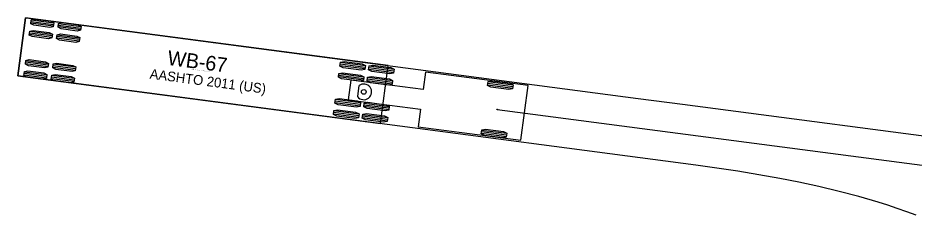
# Model space of a CAD drawing. Extents: x 2175591 to 2194071, y 76570 to 86955.
# Drawn here: x 2192726.8 to 2192856.7, y 86661.3 to 86689.9 of the extents above; entities that cross this region are included whole.
import ezdxf

# ---------------------------------------------------------------- set-up
doc = ezdxf.new("R2010")
doc.units = 0
doc.layers.add('-NOPLT', color=7, linetype='Continuous')

msp = doc.modelspace()

# ---------------------------------------------------------------- linework, layer by layer
at = {"layer": '-NOPLT'}
for p, q in [((2192727.88, 86689.91), (2192726.77, 86681.48)), ((2192780.43, 86683), (2192727.88, 86689.91)), ((2192731.93, 86688.91), (2192728.66, 86689.34)), ((2192731.96, 86689.14), (2192728.69, 86689.57)), ((2192731.9, 86688.69), (2192728.63, 86689.12)), ((2192735.87, 86688.16), (2192732.6, 86688.59)), ((2192735.9, 86688.39), (2192732.63, 86688.82)), ((2192735.93, 86688.62), (2192732.66, 86689.05)), ((2192731.69, 86687.05), (2192728.42, 86687.48)), ((2192731.72, 86687.28), (2192728.45, 86687.71)), ((2192731.75, 86687.5), (2192728.48, 86687.93)), ((2192735.66, 86686.53), (2192732.38, 86686.96)), ((2192735.69, 86686.76), (2192732.41, 86687.19)), ((2192735.72, 86686.98), (2192732.44, 86687.41)), ((2192731.13, 86682.8), (2192727.86, 86683.23)), ((2192731.16, 86683.03), (2192727.89, 86683.46)), ((2192731.19, 86683.26), (2192727.92, 86683.69)), ((2192735.13, 86682.51), (2192731.85, 86682.94)), ((2192735.16, 86682.74), (2192731.88, 86683.17)), ((2192777.07, 86682.49), (2192773.43, 86682.97)), ((2192777.1, 86682.72), (2192773.46, 86683.2)), ((2192777.13, 86682.95), (2192773.49, 86683.42)), ((2192781.29, 86682.4), (2192777.65, 86682.88)), ((2192779.32, 86674.57), (2192780.43, 86683)), ((2192780.43, 86683), (2192780.43, 86683)), ((2192726.77, 86681.48), (2192779.32, 86674.57)), ((2192730.92, 86681.17), (2192727.64, 86681.6)), ((2192730.95, 86681.39), (2192727.67, 86681.82)), ((2192730.98, 86681.62), (2192727.7, 86682.05)), ((2192734.94, 86681.1), (2192731.67, 86681.53)), ((2192735.1, 86682.28), (2192731.82, 86682.71)), ((2192776.88, 86681.08), (2192773.25, 86681.56)), ((2192776.91, 86681.31), (2192773.28, 86681.79)), ((2192781.23, 86681.94), (2192777.59, 86682.42)), ((2192781.26, 86682.17), (2192777.62, 86682.65)), ((2192785.85, 86682.03), (2192785.51, 86679.49)), ((2192800.72, 86680.07), (2192785.85, 86682.03)), ((2192734.88, 86680.65), (2192731.61, 86681.08)), ((2192734.91, 86680.87), (2192731.64, 86681.3)), ((2192776.85, 86680.86), (2192773.22, 86681.33)), ((2192775, 86680.87), (2192774.63, 86678.03)), ((2192785.51, 86679.49), (2192775, 86680.87)), ((2192781.02, 86680.31), (2192777.38, 86680.79)), ((2192781.04, 86680.54), (2192777.41, 86681.01)), ((2192781.07, 86680.76), (2192777.44, 86681.24)), ((2192798.48, 86679.67), (2192794.85, 86680.15)), ((2192798.51, 86679.9), (2192794.88, 86680.38)), ((2192798.54, 86680.13), (2192794.91, 86680.61)), ((2192776.2, 86680.08), (2192775.99, 86678.48)), ((2192799.68, 86672.14), (2192800.72, 86680.07)), ((2192800.72, 86680.07), (2192800.72, 86680.07)), ((2192776.36, 86677.11), (2192772.72, 86677.58)), ((2192776.39, 86677.33), (2192772.75, 86677.81)), ((2192776.42, 86677.56), (2192772.78, 86678.04)), ((2192774.63, 86678.03), (2192785.14, 86676.64)), ((2192776.2, 86675.92), (2192772.57, 86676.4)), ((2192780.52, 86676.56), (2192776.89, 86677.04)), ((2192780.55, 86676.78), (2192776.92, 86677.26)), ((2192780.58, 86677.01), (2192776.95, 86677.49)), ((2192785.14, 86676.64), (2192784.8, 86674.1)), ((2192796.23, 86676.63), (2192884.03, 86665.07)), ((2192776.14, 86675.47), (2192772.51, 86675.95)), ((2192776.17, 86675.7), (2192772.54, 86676.17)), ((2192780.31, 86674.92), (2192776.67, 86675.4)), ((2192780.34, 86675.15), (2192776.7, 86675.63)), ((2192780.37, 86675.38), (2192776.73, 86675.85)), ((2192784.8, 86674.1), (2192799.68, 86672.14)), ((2192797.56, 86672.65), (2192793.92, 86673.13)), ((2192797.59, 86672.88), (2192793.95, 86673.36)), ((2192797.62, 86673.11), (2192793.98, 86673.58))]:
    msp.add_line(p, q, dxfattribs=at)
for points in [[(2192856.93, 86661.28), (2192855.58, 86661.77), (2192854.21, 86662.24), (2192852.84, 86662.7), (2192851.45, 86663.14), (2192848.63, 86663.96), (2192845.77, 86664.72), (2192842.87, 86665.42), (2192839.94, 86666.05), (2192837.18, 86666.6), (2192834.14, 86667.14), (2192831.1, 86667.64), (2192828.04, 86668.11), (2192825.02, 86668.54), (2192726.77, 86681.48), (2192727.88, 86689.91), (2192727.95, 86689.9), (2192727.95, 86689.9)], [(2192727.95, 86689.9), (2192816.68, 86678.22), (2192823.09, 86677.4), (2192867.97, 86671.47)]]:
    msp.add_lwpolyline(points, dxfattribs=at)
for points in [[(2192731.97, 86689.2), (2192731.9, 86688.63), (2192731.42, 86688.52), (2192729.06, 86688.83), (2192728.63, 86689.06), (2192728.7, 86689.63), (2192729.18, 86689.74), (2192731.54, 86689.43)], [(2192731.76, 86687.56), (2192731.68, 86686.99), (2192731.2, 86686.88), (2192728.85, 86687.19), (2192728.41, 86687.42), (2192728.48, 86687.99), (2192728.97, 86688.1), (2192731.32, 86687.79)], [(2192735.94, 86688.67), (2192735.86, 86688.11), (2192735.38, 86688), (2192733.03, 86688.31), (2192732.59, 86688.54), (2192732.67, 86689.11), (2192733.15, 86689.22), (2192735.5, 86688.91)], [(2192735.72, 86687.04), (2192735.65, 86686.47), (2192735.17, 86686.36), (2192732.81, 86686.67), (2192732.38, 86686.9), (2192732.45, 86687.47), (2192732.93, 86687.58), (2192735.29, 86687.27)], [(2192731.2, 86683.31), (2192731.12, 86682.75), (2192730.64, 86682.64), (2192728.29, 86682.95), (2192727.85, 86683.18), (2192727.93, 86683.74), (2192728.41, 86683.85), (2192730.76, 86683.55)], [(2192735.16, 86682.79), (2192735.09, 86682.23), (2192734.61, 86682.11), (2192732.25, 86682.42), (2192731.82, 86682.66), (2192731.89, 86683.22), (2192732.37, 86683.33), (2192734.73, 86683.02)], [(2192777.13, 86683), (2192777.06, 86682.44), (2192776.53, 86682.33), (2192773.91, 86682.68), (2192773.42, 86682.91), (2192773.5, 86683.48), (2192774.03, 86683.59), (2192776.65, 86683.24)], [(2192781.3, 86682.46), (2192781.22, 86681.89), (2192780.69, 86681.78), (2192778.07, 86682.13), (2192777.59, 86682.37), (2192777.66, 86682.93), (2192778.19, 86683.04), (2192780.81, 86682.69)], [(2192730.98, 86681.68), (2192730.91, 86681.11), (2192730.43, 86681), (2192728.07, 86681.31), (2192727.64, 86681.54), (2192727.71, 86682.11), (2192728.19, 86682.22), (2192730.55, 86681.91)], [(2192734.95, 86681.16), (2192734.87, 86680.59), (2192734.39, 86680.48), (2192732.04, 86680.79), (2192731.6, 86681.02), (2192731.68, 86681.59), (2192732.16, 86681.7), (2192734.51, 86681.39)], [(2192776.92, 86681.37), (2192776.84, 86680.8), (2192776.31, 86680.7), (2192773.69, 86681.04), (2192773.21, 86681.28), (2192773.28, 86681.85), (2192773.81, 86681.95), (2192776.43, 86681.6)], [(2192781.08, 86680.82), (2192781.01, 86680.25), (2192780.48, 86680.15), (2192777.86, 86680.49), (2192777.37, 86680.73), (2192777.45, 86681.3), (2192777.98, 86681.4), (2192780.6, 86681.06)], [(2192798.55, 86680.19), (2192798.47, 86679.62), (2192797.94, 86679.51), (2192795.33, 86679.86), (2192794.84, 86680.1), (2192794.91, 86680.66), (2192795.44, 86680.77), (2192798.06, 86680.42)], [(2192776.42, 86677.62), (2192776.35, 86677.05), (2192775.82, 86676.95), (2192773.2, 86677.29), (2192772.71, 86677.53), (2192772.79, 86678.09), (2192773.32, 86678.2), (2192775.94, 86677.85)], [(2192780.59, 86677.07), (2192780.51, 86676.5), (2192779.98, 86676.4), (2192777.37, 86676.74), (2192776.88, 86676.98), (2192776.95, 86677.55), (2192777.48, 86677.65), (2192780.1, 86677.31)], [(2192776.21, 86675.98), (2192776.13, 86675.41), (2192775.6, 86675.31), (2192772.99, 86675.65), (2192772.5, 86675.89), (2192772.57, 86676.46), (2192773.11, 86676.56), (2192775.72, 86676.22)], [(2192780.37, 86675.43), (2192780.3, 86674.87), (2192779.77, 86674.76), (2192777.15, 86675.11), (2192776.66, 86675.34), (2192776.74, 86675.91), (2192777.27, 86676.01), (2192779.89, 86675.67)], [(2192797.62, 86673.16), (2192797.55, 86672.6), (2192797.02, 86672.49), (2192794.4, 86672.84), (2192793.91, 86673.07), (2192793.99, 86673.64), (2192794.52, 86673.74), (2192797.14, 86673.4)]]:
    msp.add_lwpolyline(points, close=True, dxfattribs=at)
for centre, radius in [((2192776.9, 86679.17), 0.34), ((2192796.23, 86676.63), 0.0417)]:
    msp.add_circle(centre, radius, dxfattribs=at)
msp.add_arc((2192776.9, 86679.17), 1.14, 217.5052, 127.5052, dxfattribs=at)

# ---------------------------------------------------------------- texts
for s, height, p in [('WB-67', 2.125, (2192748.35, 86683.1)), ('AASHTO 2011 (US)', 1.4167, (2192745.82, 86681.11)), ('(c) 2019 Transoft Solutions, Inc. All rights reserved.', 0.085, (2192751.88, 86682.42))]:
    msp.add_text(s, height=height, rotation=352.5052, dxfattribs=at).set_placement(p)

doc.saveas('drawing.dxf')
